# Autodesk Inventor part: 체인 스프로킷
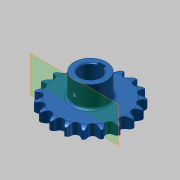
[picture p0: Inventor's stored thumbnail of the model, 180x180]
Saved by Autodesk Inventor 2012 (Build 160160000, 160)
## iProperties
Created: 2014-11
Part Number: 체인 스프로킷
Material: 강
Document SubType Name: Modeling
Designer: KYOUNG IL JANG
Density: 7.85 g/cm^3
Mass: 738.264 g
Surface Area: 236.923 cm^2
Volume: 94.0463 cm^3
CustomPartVersion: 1
Company: 한국ATC센터
Author: KYOUNG IL JANG
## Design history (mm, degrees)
sketch "이론적 톱니 프로파일"
  geometry: L1 (0, 0)-(0, 45.567); L2 (0, 0)-(14.795, 43.098); L3 (0, 45.567)-(14.795, 43.098); L4 (0, 45.567)-(5.661, 50.015); L5 (5.661, 50.015)-(-5.141, 45.406); L6 (-12.428, 43.493)-(-5.573, 46.417); L7 (-5.141, 45.406)-(-5.573, 46.417); L8 (5.573, 46.417)-(5.141, 45.406); L9 (0, 0)-(8.138, 48.771); A1 r 45.567 centre (0, 0) between (0, 45.567) and (14.795, 43.098); A2 r 49.445 centre (0, 0) between (7.302, 48.903) and (-7.302, 48.903); A3 r 4.545 centre (0, 45.567) between (-3.574, 42.758) and (3.574, 42.758); A4 r 7.453 centre (12.428, 43.493) between (7.302, 48.903) and (5.573, 46.417); A5 r 7.453 centre (-12.428, 43.493) between (-5.573, 46.417) and (-7.302, 48.903); A6 r 11.745 centre (5.661, 50.015) between (-5.141, 45.406) and (-3.574, 42.758); A7 r 11.745 centre (-5.661, 50.015) between (3.574, 42.758) and (5.141, 45.406); 2 further points
  constraints: 18 end point, 15 point on circle, 7 centre point, 3 coincident, 3 point on line, 3 symmetric about line, 3 tangent, 1 equal radius, 1 midpoint, 1 parallel, 1 vertical, 1 other
  dimensions: "d0" = 91.13301 diameter of A1 (computed from da_p, da_z); "d2" = 18.9474 deg angle of L2 L1 (computed from da_z); "d3" = 4.545 radius of A3 (= 0.5 x da_Dr + da_SC); "d10" = 128.158 deg angle of L4 L1 (computed from da_z); "d11" = 15.0526 deg angle of L5 L4 (computed from da_z); "d12" = 7.2 distance of L3.start L4.end (= 0.8 x da_Dr); "d13" = 11.745 distance of L4.end L5.end (= 1.3 x da_Dr + da_SC); "d14" = 12.6 distance of A4.centre L1.end (= 1.4 x da_Dr); "d23" = 4.5 distance from line of L9.end L3 (= da_Ha)
sketch "톱니 프로파일"
  geometry: L1 (0, 0)-(0, 45.567); L2 (0, 45.567)-(4.203, 43.837); L3 (0, 45.567)-(-4.203, 43.837); A1 r 4.545 centre (0, 45.567) between (-4.203, 43.837) and (4.203, 43.837); A2 r 22.68 centre (25.176, 35.206) between (7.12, 48.93) and (4.203, 43.837); A3 r 22.68 centre (-25.176, 35.206) between (-4.203, 43.837) and (-7.12, 48.93); A4 r 49.445 centre (0, 0) between (-7.12, 48.93) and (7.12, 48.93) reference; 1 further point
  constraints: 9 point on circle, 6 end point, 3 centre point, 2 tangent, 1 coincident, 1 equal radius, 1 vertical, 1 other
  dimensions: "d44" = 135.263 deg angle of L3 L2 (= da_Alfa); "d45" = 22.68 radius of A2 (= da_Re); "d46" = 4.545 radius of A1 (= da_Ri)
sketch "단면 프로파일"
  geometry: L1 (49.445, 0)-(-49.445, 0) reference; L2 (33.265, 6.65)-(-33.265, 6.65); L3 (-33.265, 6.65)-(-33.265, -6.65); L4 (-33.265, -6.65)-(33.265, -6.65); L5 (33.265, -6.65)-(33.265, 6.65); L6 (33.265, 6.65)-(49.445, 6.65); L7 (49.445, 6.65)-(49.445, -6.65); L8 (49.445, -6.65)-(33.265, -6.65); L9 (33.265, -6.65)-(33.265, 6.65); L10 (42.183, 6.65)-(0, 6.65); L11 (0, 6.65)-(0, -6.65); L12 (0, -6.65)-(42.183, -6.65); L13 (0, 6.65)-(0, -6.65); L14 (49.445, 4.775)-(49.445, -4.775); A1 r 15 centre (42.183, -8.35) between (49.445, 4.775) and (42.183, 6.65); A2 r 15 centre (42.183, 8.35) between (42.183, -6.65) and (49.445, -4.775); 2 further points
  constraints: 26 end point, 7 midpoint, 5 perpendicular, 4 parallel, 4 point on circle, 3 point on line, 3 symmetric about line, 2 centre point, 2 horizontal, 2 tangent, 1 collinear, 1 other
  dimensions: "d30" = 13.3 distance between parallel lines of L8 L6 (= da_Bf); "d31" = 66.53007 distance between parallel lines of L3 L5 (= da_Ds); "d32" = 13.3 distance between parallel lines of L4 L2 (= da_Bs); "d33" = 1.875 distance from line of L14.start L6 (= da_Ba); "d34" = 15 radius of A1 (= da_Rx); "d43" = 6.65 distance between parallel lines of L4 L1 (computed from da_k, da_pt, da_Bs)
revolve "슈라우드" stored, may be unused: angle "d36" = 90 deg
revolve "스트랜드" stored, may be unused: angle "d37" = 90 deg
extrude "이론적 톱니" cut sketch "이론적 톱니 프로파일" stored distance "d18" = 10; taper "d19" = 0 deg; dims "d49" = 0, "form_type" = 0 [user parameter]
extrude "톱니" cut sketch "톱니 프로파일" stored distance "d47" = 10; taper "d48" = 0 deg; dims "d50" = 10, "form_type" = 0 [user parameter]
node "타이밍 평면"
node "작업 평면3"
sketch "스케치5"
  geometry: C1 r 20 at (0, -45.567); 1 further point
  constraints: 1 centre point, 1 coincident
  dimensions: "d52" = 40 diameter of C1
extrude "돌출4" join sketch "스케치5" stored distance "d53" = 10; taper "d54" = 0 deg
sketch "스케치6"
  geometry: L1 (4, 11.843)-(4, 16.5); L2 (4, 16.5)-(-4, 16.5); L3 (-4, 16.5)-(-4, 11.843); A1 r 12.5 centre (0, 0) between (4, 11.843) and (-4, 11.843); 1 further point
  constraints: 6 end point, 2 parallel, 2 point on circle, 1 centre point, 1 coincident, 1 perpendicular, 1 vertical
  dimensions: "d55" = 25 diameter of A1; "d56" = 29 dimension on A1 L2 (computed from d55); "d57" = 8 distance of L1.end L2.end
extrude "돌출5" cut sketch "스케치6" stored distance "d58" = 10; taper "d59" = 0 deg
fillet "모깎기2" dims "d60" = 3
chamfer "모따기1" distance "d61" = 1; stored, may be unused: second distance "d62" = 2, angle "d63" = 45 deg
node "작업 평면4"
sketch "스케치7"
  geometry: L1 (-13.5, -13.3)-(13.5, -13.3) reference; 4 further points
  constraints: 1 vertical alignment
  dimensions: "d65" = 25 distance from line of point (0, 11.7) L1
hole "구멍1" sketch "스케치7" at (0, 11.7) diameter "d66" = 5; stored, may be unused: countersink angle "d70" = 90 deg, drill point angle "d72" = 118 deg; dims "d67" = 6, "d68" = 4, "d69" = 2, "d71" = 8
feature "스레드1" dims "d73" = 10, "d74" = 0
body "Solid1"
pattern_linear "스트랜드 패턴" dims "d40" = 24 (= da_pt)
pattern_circular "톱니 패턴" dims angle "d21" = 360 deg
other parameters: "da_p" = 15 [user parameter; used in 1 equation term], "da_Dr" = 9 [user parameter; used in 4 equation terms], "da_SC" = 0.045 [user parameter; used in 2 equation terms], "da_Ha" = 4.5 [user parameter; used in 1 equation term], "da_pt" = 24 [user parameter; used in 2 equation terms], "da_Bf" = 13.3 [user parameter; used in 1 equation term], "d28" = 0, "d29" = 0, "da_Ba" = 1.875 [user parameter; used in 1 equation term], "da_Rx" = 15 [user parameter; used in 1 equation term], "da_Ra" = 0.6 [user parameter], "da_Bs" = 13.3 [user parameter; used in 2 equation terms], "da_Ds" = 66.53007 [user parameter; used in 1 equation term], "d42" = 0, "da_Re" = 22.68 [user parameter; used in 1 equation term], "da_Ri" = 4.545 [user parameter; used in 1 equation term], "da_Alfa" = 135.263 deg [user parameter; used in 1 equation term]
